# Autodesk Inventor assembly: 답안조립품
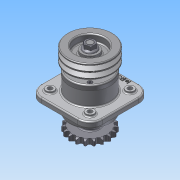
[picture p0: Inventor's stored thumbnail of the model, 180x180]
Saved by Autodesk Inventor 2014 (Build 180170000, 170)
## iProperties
Created: 2015-09
Part Number: 답안조립품
Document SubType Name: Assembly
Designer: study
Author: study
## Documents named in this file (12)
- C:\Users\study\Desktop\450909V1006\답안조립품.iam
- C:\Users\study\Desktop\450909V1006\1-본체.ipt
- C:\Users\study\Desktop\450909V1006\2-커버.ipt
- C:\Users\study\Desktop\450909V1006\6-베어링 6206.ipt
- C:\Users\study\Desktop\450909V1006\8-오일실 30x42.ipt
- C:\Users\study\Desktop\450909V1006\10-M6.ipt
- C:\Users\study\Desktop\450909V1006\3-축.ipt
- C:\Users\study\Desktop\450909V1006\5-체인 스프로킷.ipt
- C:\Users\study\Desktop\450909V1006\9-M16-너트.ipt
- C:\Users\study\Desktop\450909V1006\11-키 6x6.ipt
- C:\Users\study\Desktop\450909V1006\4-V벨트풀리.ipt
- C:\Users\study\Desktop\450909V1006\7-부시.ipt
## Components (23 placed, 11 different names)
1. 1-본체:1
2. 2-커버:1
3. 6-베어링 6206:1
4. 8-8-오일실 30x42:1
5. 3-축:1 — 각도:1, 각도:3
6. 2-커버:2
7. 6-베어링 6206:2
8. 8-8-오일실 30x42:2
9. 5-체인 스프로킷:1 — 각도:2
10. 9-M16 너트:1
11. 11-키 6x6:1 — 각도:1, 각도:2
12. 4-V벨트풀리:1 — 각도:4
13. 9-M16 너트:2
14. 11-키 6x6:2 — 각도:3, 각도:4
15. 7-부시:1
16. 10-M6:1
17. 10-M6:2
18. 10-M6:3
19. 10-M6:4
20. 10-M6:5
21. 10-M6:6
22. 10-M6:7
23. 10-M6:8
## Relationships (4: Angle 4)
- 각도:1 [Angle]: 3-축:1 ↔ 11-키 6x6:1
- 각도:2 [Angle]: 5-체인 스프로킷:1 ↔ 11-키 6x6:1
- 각도:3 [Angle]: 3-축:1 ↔ 11-키 6x6:2
- 각도:4 [Angle]: 4-V벨트풀리:1 ↔ 11-키 6x6:2
